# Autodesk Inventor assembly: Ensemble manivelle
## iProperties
Shininess: 41.0
Length Units: 11269
Angle Units: 11279
Time Units: 11290
Mass Units: 11283
Length Display Precision: 3
Angle Display Precision: 2
Created: 2002-11
Part Number: Ensemble manivelle
Document SubType Name: Assemblage
Designer: poste-2
Density: 0.0
Volumn: 0.0
Area: 0.0
PropertySet Name: Model Information
Control State: 0
Master: False
Checked Out: False
Author: poste-2
